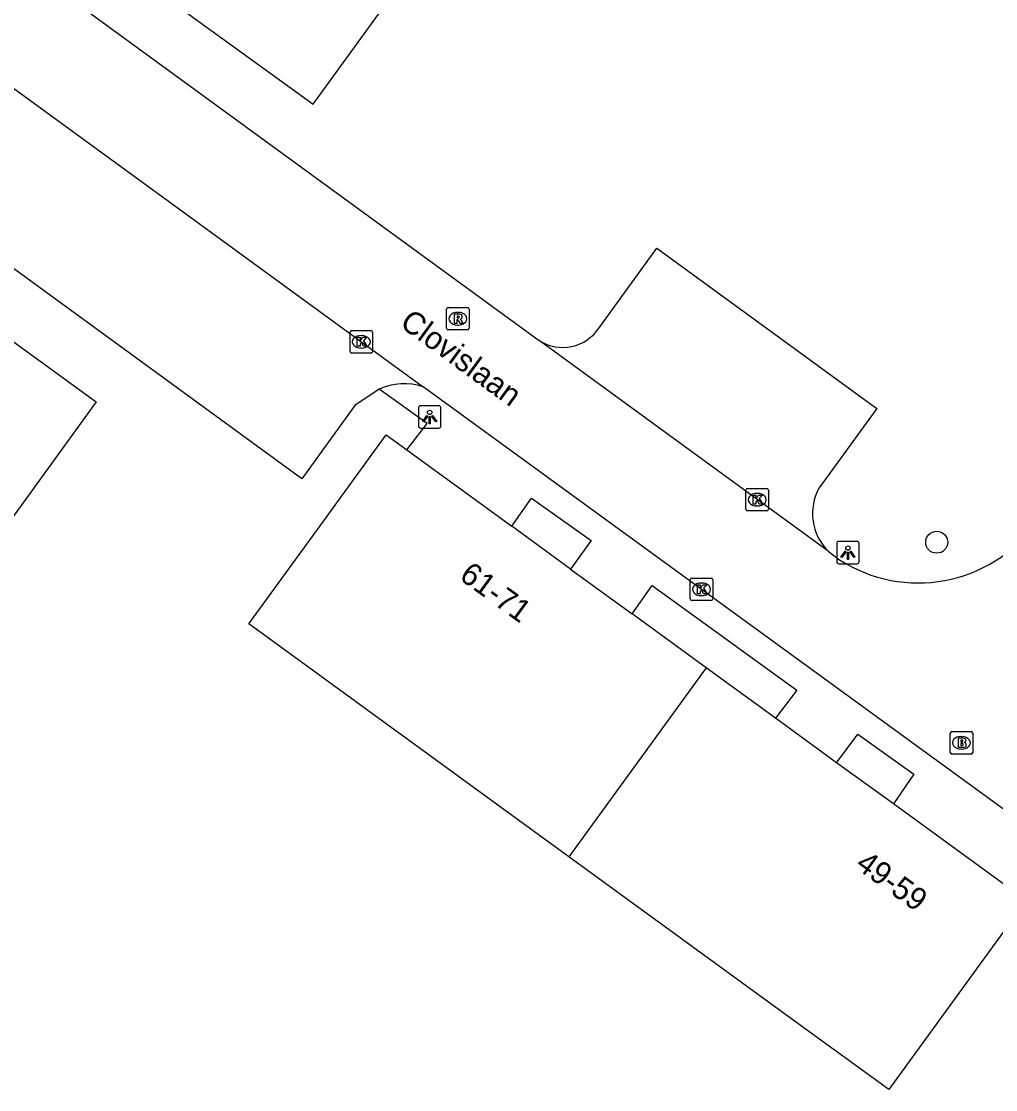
# Model space of a CAD drawing. Extents: x 159675 to 160530, y 382179 to 382901.
# Drawn here: x 160295.75 to 160339.08, y 382540.97 to 382588.46 of the extents above; entities that cross this region are included whole.
import ezdxf

# ---------------------------------------------------------------- set-up
doc = ezdxf.new("R2010")
doc.units = 0
for name, color, linetype in [('IMGEO_Boom', 7, 'Continuous'), ('IMGEO_Brandkraan', 7, 'Continuous'), ('IMGEO_Kolk', 7, 'Continuous'), ('IMGEO_Lichtpunt', 7, 'Continuous'), ('IMGEO_Openbare_ruimte_label', 7, 'Continuous'), ('IMGEO_Pand', 7, 'Continuous'), ('IMGEO_Pand_nummerreeks', 7, 'Continuous'), ('IMGEO_Parkeervlak_open', 7, 'Continuous'), ('IMGEO_Rijbaan_lokaal_open', 7, 'Continuous'), ('IMGEO_Rioolput', 7, 'Continuous'), ('IMGEO_Voetpad_open', 7, 'Continuous')]:
    doc.layers.add(name, color=color, linetype=linetype)

msp = doc.modelspace()

# ---------------------------------------------------------------- linework, layer by layer
at = {"layer": 'IMGEO_Boom'}
msp.add_circle((160336.46, 382565.304), 0.489, dxfattribs=at)
at = {"layer": 'IMGEO_Brandkraan'}
for p, q in [((160337.057, 382555.962), (160337.057, 382556.814)), ((160337.132, 382556.888), (160337.984, 382556.888)), ((160337.545, 382556.668), (160337.57, 382556.668)), ((160338.058, 382556.814), (160338.058, 382555.962)), ((160337.568, 382556.108), (160337.543, 382556.108)), ((160337.984, 382555.888), (160337.132, 382555.888))]:
    msp.add_line(p, q, dxfattribs=at)
for points in [[(160337.057, 382555.962), (160337.057, 382556.814)], [(160337.132, 382556.888), (160337.984, 382556.888)], [(160337.405, 382556.588), (160337.405, 382556.188), (160337.618, 382556.188)], [(160337.636, 382556.588), (160337.405, 382556.588)], [(160337.584, 382556.507), (160337.53, 382556.507), (160337.53, 382556.431)], [(160338.058, 382556.814), (160338.058, 382555.962)], [(160337.53, 382556.431), (160337.583, 382556.431)], [(160337.592, 382556.355), (160337.53, 382556.355), (160337.53, 382556.274)], [(160337.53, 382556.274), (160337.592, 382556.274)], [(160337.984, 382555.888), (160337.132, 382555.888)]]:
    msp.add_lwpolyline(points, dxfattribs=at)
for centre, radius, start, end in [((160337.134, 382556.812), 0.0765, 91.552, 178.448), ((160337.134, 382556.812), 0.0765, 91.552, 178.448), ((160337.585, 382556.469), 0.0379, 267.8285, 90.9355), ((160337.64, 382556.443), 0.145, 59.4692, 91.5367), ((160337.665, 382556.49), 0.0922, 285.5137, 58.1501), ((160337.982, 382556.812), 0.0765, 1.552, 88.448), ((160337.982, 382556.812), 0.0765, 1.552, 88.448), ((160337.593, 382556.314), 0.0404, 269.8759, 90.5077), ((160337.624, 382556.439), 0.251, 268.6676, 293.5347), ((160337.67, 382556.298), 0.105, 301.3115, 78.989), ((160337.134, 382555.964), 0.0765, 181.552, 268.448), ((160337.134, 382555.964), 0.0765, 181.552, 268.448), ((160337.982, 382555.964), 0.0765, 271.552, 358.448), ((160337.982, 382555.964), 0.0765, 271.552, 358.448)]:
    msp.add_arc(centre, radius, start, end, dxfattribs=at)
for centre, major_axis, ratio, start_param, end_param in [((160337.544, 382556.388), (-0.387, 0.002), 0.722429, 4.712389, 7.853982), ((160337.569, 382556.388), (-0.39, 0.002), 0.717154, 1.570796, 4.712389)]:
    msp.add_ellipse(centre, major_axis=major_axis, ratio=ratio, start_param=start_param, end_param=end_param, dxfattribs=at)
at = {"layer": 'IMGEO_Kolk'}
for p, q in [((160310.369, 382573.789), (160310.369, 382574.641)), ((160310.444, 382574.715), (160311.296, 382574.715)), ((160311.37, 382574.641), (160311.37, 382573.789)), ((160310.857, 382574.495), (160310.882, 382574.495)), ((160311.296, 382573.715), (160310.444, 382573.715)), ((160310.88, 382573.935), (160310.855, 382573.935)), ((160327.975, 382566.77), (160327.975, 382567.622)), ((160328.05, 382567.696), (160328.902, 382567.696)), ((160328.463, 382567.476), (160328.488, 382567.476)), ((160328.976, 382567.622), (160328.976, 382566.77)), ((160328.486, 382566.916), (160328.461, 382566.916)), ((160328.902, 382566.696), (160328.05, 382566.696)), ((160325.499, 382562.784), (160325.499, 382563.636)), ((160325.574, 382563.71), (160326.426, 382563.71)), ((160326.5, 382563.636), (160326.5, 382562.784)), ((160325.987, 382563.49), (160326.012, 382563.49)), ((160326.426, 382562.71), (160325.574, 382562.71)), ((160326.01, 382562.93), (160325.985, 382562.93))]:
    msp.add_line(p, q, dxfattribs=at)
for points in [[(160310.369, 382573.789), (160310.369, 382574.641)], [(160310.444, 382574.715), (160311.296, 382574.715)], [(160311.37, 382574.641), (160311.37, 382573.789)], [(160310.69, 382574.415), (160310.813, 382574.415), (160310.813, 382574.264), (160310.943, 382574.415), (160311.107, 382574.415), (160310.961, 382574.264), (160311.114, 382574.015), (160310.962, 382574.015), (160310.877, 382574.179), (160310.813, 382574.112), (160310.813, 382574.015), (160310.69, 382574.015), (160310.69, 382574.415)], [(160311.296, 382573.715), (160310.444, 382573.715)], [(160327.975, 382566.77), (160327.975, 382567.622)], [(160328.05, 382567.696), (160328.902, 382567.696)], [(160328.296, 382567.396), (160328.419, 382567.396), (160328.419, 382567.245), (160328.549, 382567.396), (160328.713, 382567.396), (160328.567, 382567.245), (160328.72, 382566.996), (160328.568, 382566.996), (160328.483, 382567.16), (160328.419, 382567.093), (160328.419, 382566.996), (160328.296, 382566.996), (160328.296, 382567.396)], [(160328.976, 382567.622), (160328.976, 382566.77)], [(160328.902, 382566.696), (160328.05, 382566.696)], [(160325.499, 382562.784), (160325.499, 382563.636)], [(160325.574, 382563.71), (160326.426, 382563.71)], [(160326.5, 382563.636), (160326.5, 382562.784)], [(160325.82, 382563.41), (160325.943, 382563.41), (160325.943, 382563.259), (160326.073, 382563.41), (160326.237, 382563.41), (160326.091, 382563.259), (160326.244, 382563.01), (160326.092, 382563.01), (160326.007, 382563.174), (160325.943, 382563.107), (160325.943, 382563.01), (160325.82, 382563.01), (160325.82, 382563.41)], [(160326.426, 382562.71), (160325.574, 382562.71)]]:
    msp.add_lwpolyline(points, dxfattribs=at)
for centre, start, end in [((160310.446, 382574.639), 91.552, 178.448), ((160310.446, 382574.639), 91.552, 178.448), ((160311.294, 382574.639), 1.552, 88.448), ((160311.294, 382574.639), 1.552, 88.448), ((160310.446, 382573.791), 181.552, 268.448), ((160310.446, 382573.791), 181.552, 268.448), ((160311.294, 382573.791), 271.552, 358.448), ((160311.294, 382573.791), 271.552, 358.448), ((160328.052, 382567.62), 91.552, 178.448), ((160328.052, 382567.62), 91.552, 178.448), ((160328.9, 382567.62), 1.552, 88.448), ((160328.9, 382567.62), 1.552, 88.448), ((160328.052, 382566.772), 181.552, 268.448), ((160328.052, 382566.772), 181.552, 268.448), ((160328.9, 382566.772), 271.552, 358.448), ((160328.9, 382566.772), 271.552, 358.448), ((160325.576, 382563.634), 91.552, 178.448), ((160325.576, 382563.634), 91.552, 178.448), ((160326.424, 382563.634), 1.552, 88.448), ((160326.424, 382563.634), 1.552, 88.448), ((160325.576, 382562.786), 181.552, 268.448), ((160325.576, 382562.786), 181.552, 268.448), ((160326.424, 382562.786), 271.552, 358.448), ((160326.424, 382562.786), 271.552, 358.448)]:
    msp.add_arc(centre, 0.0765, start, end, dxfattribs=at)
for centre, major_axis, ratio, start_param, end_param in [((160310.856, 382574.215), (-0.387, 0.002), 0.722429, 4.712389, 7.853982), ((160310.881, 382574.215), (-0.39, 0.002), 0.717154, 1.570796, 4.712389), ((160328.462, 382567.196), (-0.387, 0.002), 0.722429, 4.712389, 7.853982), ((160328.487, 382567.196), (-0.39, 0.002), 0.717154, 1.570796, 4.712389), ((160325.986, 382563.21), (-0.387, 0.002), 0.722429, 4.712389, 7.853982), ((160326.011, 382563.21), (-0.39, 0.002), 0.717154, 1.570796, 4.712389)]:
    msp.add_ellipse(centre, major_axis=major_axis, ratio=ratio, start_param=start_param, end_param=end_param, dxfattribs=at)
at = {"layer": 'IMGEO_Lichtpunt'}
for p, q in [((160313.412, 382571.277), (160313.412, 382570.47)), ((160313.412, 382571.277), (160313.412, 382570.47)), ((160314.314, 382571.372), (160313.506, 382571.372)), ((160314.314, 382571.372), (160313.506, 382571.372)), ((160314.408, 382570.47), (160314.408, 382571.277)), ((160314.408, 382570.47), (160314.408, 382571.277)), ((160313.506, 382570.376), (160314.314, 382570.376)), ((160313.506, 382570.376), (160314.314, 382570.376)), ((160332.011, 382565.245), (160332.011, 382564.438)), ((160332.011, 382565.245), (160332.011, 382564.438)), ((160332.913, 382565.34), (160332.105, 382565.34)), ((160332.913, 382565.34), (160332.105, 382565.34)), ((160333.007, 382564.438), (160333.007, 382565.245)), ((160333.007, 382564.438), (160333.007, 382565.245)), ((160332.105, 382564.344), (160332.913, 382564.344)), ((160332.105, 382564.344), (160332.913, 382564.344))]:
    msp.add_line(p, q, dxfattribs=at)
for points in [[(160313.786, 382570.941), (160313.825, 382570.913), (160313.637, 382570.651), (160313.599, 382570.678), (160313.786, 382570.941)], [(160313.888, 382570.893), (160313.935, 382570.893), (160313.935, 382570.571), (160313.888, 382570.571), (160313.888, 382570.893)], [(160313.998, 382570.913), (160314.036, 382570.94), (160314.223, 382570.678), (160314.184, 382570.65), (160313.998, 382570.913)], [(160332.385, 382564.909), (160332.424, 382564.881), (160332.236, 382564.619), (160332.198, 382564.646), (160332.385, 382564.909)], [(160332.487, 382564.861), (160332.534, 382564.861), (160332.534, 382564.539), (160332.487, 382564.539), (160332.487, 382564.861)], [(160332.597, 382564.881), (160332.635, 382564.908), (160332.822, 382564.646), (160332.783, 382564.618), (160332.597, 382564.881)]]:
    msp.add_lwpolyline(points, dxfattribs=at)
for centre in [(160313.911, 382571.075), (160332.51, 382565.043)]:
    msp.add_circle(centre, 0.0994, dxfattribs=at)
for centre, start, end in [((160313.506, 382571.277), 90, 180), ((160313.506, 382571.277), 90, 180), ((160314.314, 382571.277), 0, 90), ((160314.314, 382571.277), 0, 90), ((160313.506, 382570.47), 180, 270), ((160313.506, 382570.47), 180, 270), ((160314.314, 382570.47), 270, 0), ((160314.314, 382570.47), 270, 360), ((160332.105, 382565.245), 90, 180), ((160332.105, 382565.245), 90, 180), ((160332.913, 382565.245), 0, 90), ((160332.913, 382565.245), 0, 90), ((160332.105, 382564.438), 180, 270), ((160332.105, 382564.438), 180, 270), ((160332.913, 382564.438), 270, 0), ((160332.913, 382564.438), 270, 360)]:
    msp.add_arc(centre, 0.0946, start, end, dxfattribs=at)
at = {"layer": 'IMGEO_Pand'}
for points in [[(160300.591, 382591.227), (160300.328, 382590.864), (160308.724, 382584.776), (160319.055, 382599.025)], [(160290.265, 382577.019), (160290.699, 382577.618), (160299.084, 382571.539), (160288.827, 382557.394)], [(160320.097, 382551.321), (160305.863, 382561.673), (160309.033, 382566.031), (160311.974, 382570.074), (160312.894, 382569.405)], [(160312.894, 382569.405), (160317.558, 382566.013)], [(160320.177, 382564.108), (160317.558, 382566.013)], [(160320.177, 382564.108), (160322.918, 382562.114)], [(160326.208, 382559.722), (160322.918, 382562.114)], [(160326.208, 382559.722), (160320.097, 382551.321)], [(160329.295, 382557.477), (160326.208, 382559.722)], [(160332.008, 382555.503), (160329.295, 382557.477)], [(160334.533, 382553.667), (160332.008, 382555.503)], [(160340.442, 382549.369), (160334.533, 382553.667)], [(160340.442, 382549.369), (160334.331, 382540.968), (160330.288, 382543.909), (160320.097, 382551.321)]]:
    msp.add_lwpolyline(points, dxfattribs=at)
at = {"layer": 'IMGEO_Parkeervlak_open'}
for points in [[(160311.658, 382572.109), (160310.584, 382571.385), (160308.218, 382568.127), (160290.343, 382581.143)], [(160321.442, 382574.841), (160324.016, 382578.372), (160333.793, 382571.243), (160331.23, 382567.728)]]:
    msp.add_lwpolyline(points, dxfattribs=at)
for centre, radius, start, end in [((160319.827, 382575.885), 1.923, 236.9416, 327.1304), ((160333.326, 382566.58), 2.39, 151.2887, 224.5853)]:
    msp.add_arc(centre, radius, start, end, dxfattribs=at)
at = {"layer": 'IMGEO_Rijbaan_lokaal_open'}
for points in [[(160296.348, 382590.626), (160318.778, 382574.273)], [(160293.086, 382587.159), (160313.617, 382572.218)], [(160331.624, 382564.902), (160318.778, 382574.273)], [(160341.99, 382551.571), (160313.617, 382572.218)]]:
    msp.add_lwpolyline(points, dxfattribs=at)
msp.add_arc((160335.641, 382569.925), 6.432, 231.3507, 318.9111, dxfattribs=at)
at = {"layer": 'IMGEO_Rioolput'}
for p, q in [((160314.664, 382574.814), (160314.664, 382575.666)), ((160314.739, 382575.74), (160315.591, 382575.74)), ((160315.152, 382575.52), (160315.177, 382575.52)), ((160315.665, 382575.666), (160315.665, 382574.814)), ((160315.591, 382574.74), (160314.739, 382574.74)), ((160315.175, 382574.96), (160315.15, 382574.96))]:
    msp.add_line(p, q, dxfattribs=at)
for points in [[(160314.664, 382574.814), (160314.664, 382575.666)], [(160314.739, 382575.74), (160315.591, 382575.74)], [(160315.665, 382575.666), (160315.665, 382574.814)], [(160315.253, 382575.438), (160315.001, 382575.44), (160315.001, 382575.04)], [(160315.001, 382575.04), (160315.125, 382575.04), (160315.125, 382575.202), (160315.136, 382575.202)], [(160315.179, 382575.359), (160315.125, 382575.359), (160315.125, 382575.278)], [(160315.125, 382575.278), (160315.177, 382575.278)], [(160315.183, 382575.173), (160315.254, 382575.04), (160315.394, 382575.04), (160315.329, 382575.166)], [(160315.591, 382574.74), (160314.739, 382574.74)]]:
    msp.add_lwpolyline(points, dxfattribs=at)
for centre, radius, start, end in [((160314.741, 382575.664), 0.0765, 91.552, 178.448), ((160314.741, 382575.664), 0.0765, 91.552, 178.448), ((160315.589, 382575.664), 0.0765, 1.552, 88.448), ((160315.589, 382575.664), 0.0765, 1.552, 88.448), ((160315.135, 382575.149), 0.0533, 26.0293, 88.6989), ((160315.161, 382575.467), 0.19, 274.7715, 282.9687), ((160315.185, 382575.263), 0.0964, 77.0061, 93.1865), ((160315.199, 382575.32), 0.0378, 276.6634, 79.6772), ((160315.252, 382575.328), 0.109, 350.3612, 89.416), ((160315.25, 382575.328), 0.112, 277.5842, 350.9817), ((160315.234, 382575.113), 0.108, 29.5134, 73.7905), ((160314.741, 382574.816), 0.0765, 181.552, 268.448), ((160314.741, 382574.816), 0.0765, 181.552, 268.448), ((160315.589, 382574.816), 0.0765, 271.552, 358.448), ((160315.589, 382574.816), 0.0765, 271.552, 358.448)]:
    msp.add_arc(centre, radius, start, end, dxfattribs=at)
for centre, major_axis, ratio, start_param, end_param in [((160315.151, 382575.24), (-0.387, 0.002), 0.722429, 4.712389, 7.853982), ((160315.176, 382575.24), (-0.39, 0.002), 0.717154, 1.570796, 4.712389)]:
    msp.add_ellipse(centre, major_axis=major_axis, ratio=ratio, start_param=start_param, end_param=end_param, dxfattribs=at)
at = {"layer": 'IMGEO_Voetpad_open'}
for points in [[(160312.894, 382569.405), (160313.791, 382570.579), (160311.658, 382572.109)], [(160317.558, 382566.013), (160318.431, 382567.266), (160321.094, 382565.384), (160320.177, 382564.108)], [(160322.918, 382562.114), (160323.808, 382563.387), (160330.237, 382558.731), (160329.295, 382557.477)], [(160332.008, 382555.503), (160332.951, 382556.772), (160335.437, 382554.991), (160334.533, 382553.667)]]:
    msp.add_lwpolyline(points, dxfattribs=at)
msp.add_arc((160312.78, 382569.596), 2.752, 72.2994, 114.07, dxfattribs=at)

# ---------------------------------------------------------------- texts
at = {"layer": 'IMGEO_Openbare_ruimte_label'}
msp.add_text('Clovislaan', height=1, rotation=323.9094, dxfattribs=at).set_placement((160312.529, 382574.925))
at = {"layer": 'IMGEO_Pand_nummerreeks'}
for s, rotation, p in [('61-71', 323.9718, (160315.178, 382563.688)), ('49-59', 324.0579, (160332.795, 382550.852))]:
    msp.add_text(s, height=1, rotation=rotation, dxfattribs=at).set_placement(p)

doc.saveas('drawing.dxf')
